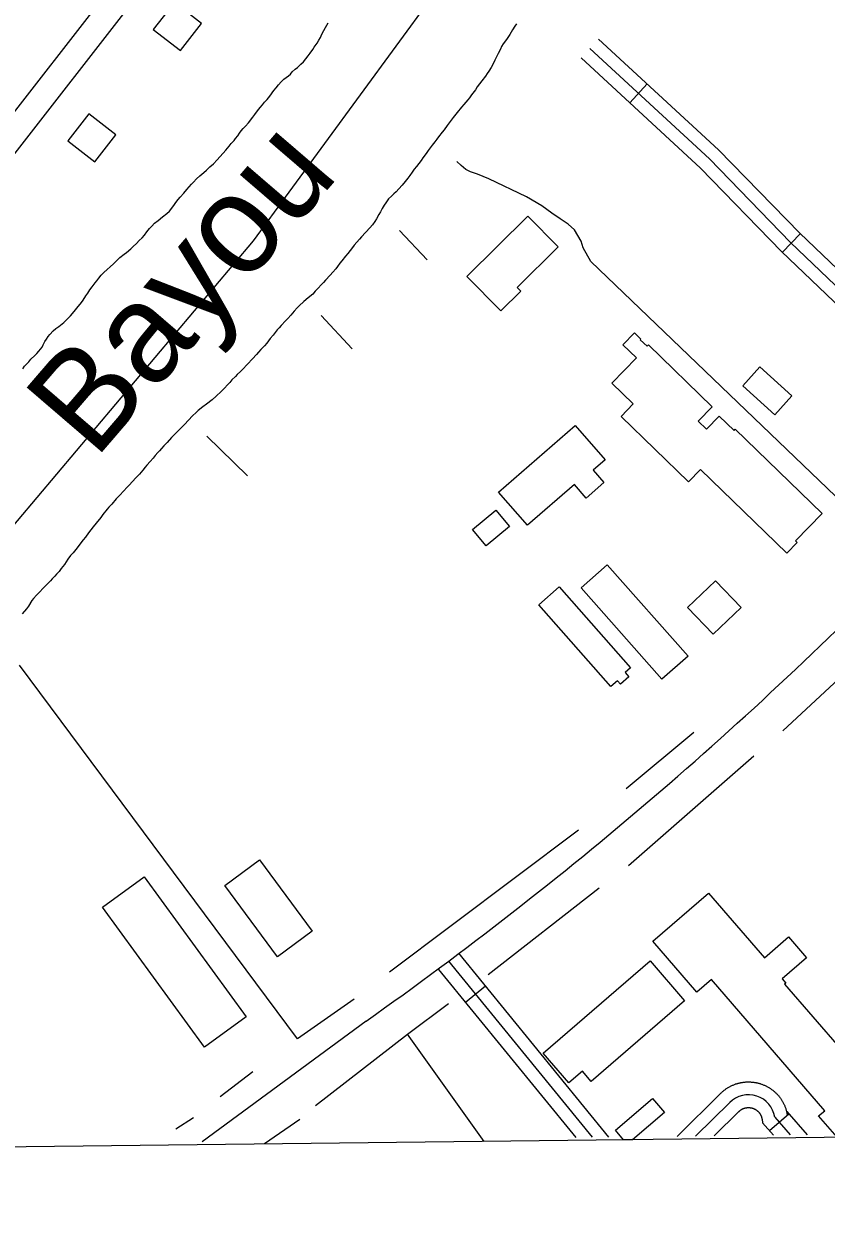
# Model space of a CAD drawing. Extents: x 3683402 to 3721514, y 487807 to 513565.
# Drawn here: x 3694421 to 3695359, y 493222 to 494613 of the extents above; entities that cross this region are included whole.
import ezdxf

# ---------------------------------------------------------------- set-up
doc = ezdxf.new("R2010")
doc.units = 0
for name, color, linetype in [('V-BLDG-OTLN', 7, 'Continuous'), ('V-GRID-FRAM', 7, 'Continuous'), ('V-RIVR-IDEN', 7, 'Continuous'), ('V-ROAD-CNTR', 7, 'Continuous'), ('V-TOPO-BNDY', 7, 'Continuous'), ('V-TOPO-SHOR', 7, 'Continuous')]:
    doc.layers.add(name, color=color, linetype=linetype)

msp = doc.modelspace()

# ---------------------------------------------------------------- linework, layer by layer
at = {"layer": 'V-BLDG-OTLN'}
for p, q in [((3695156.5, 493540.8), (3695221.6, 493597.1)), ((3695221.6, 493597.1), (3695286.8, 493521.6)), ((3695207.9, 493481.4), (3695156.5, 493540.8)), ((3695286.8, 493521.6), (3695314.8, 493545.8)), ((3695314.8, 493545.8), (3695335.9, 493521.4)), ((3695335.9, 493521.4), (3695307.6, 493496.9)), ((3695225, 493496), (3695207.9, 493481.4)), ((3695357.4, 493342.8), (3695225, 493496)), ((3695307.6, 493496.9), (3695311.8, 493492)), ((3695311.8, 493492), (3695310.3, 493490.6)), ((3695310.3, 493490.6), (3695376.3, 493414.2)), ((3695112.6, 493320.2), (3695156.1, 493357.2)), ((3695156.1, 493357.2), (3695170.1, 493340.8)), ((3695350.1, 493336.6), (3695357.4, 493342.8)), ((3695170.1, 493340.8), (3695132.5, 493308.9)), ((3695371.7, 493311.7), (3695350.1, 493336.6)), ((3695122.3, 493308.8), (3695112.6, 493320.2)), ((3695132.5, 493308.9), (3695122.3, 493308.8))]:
    msp.add_line(p, q, dxfattribs=at)
for points in [[(3694597.3, 494637.9), (3694572.7, 494606.4), (3694604.3, 494581.8), (3694628.9, 494613.4)], [(3694497.3, 494507.8), (3694472.7, 494476.2), (3694504.3, 494451.6), (3694528.8, 494483.2)], [(3694939.1, 494317.7), (3695010.3, 494388.2), (3695045.7, 494352.5), (3694997.7, 494304.9), (3695002.1, 494300.5), (3694978.9, 494277.5)], [(3695354.3, 494040.6), (3695323.2, 494008.6), (3695325, 494006.8), (3695312.9, 493994.4), (3695212.2, 494092.3), (3695197.9, 494077.6), (3695119.3, 494154.1), (3695133.6, 494168.8), (3695108.5, 494193.2), (3695137.2, 494222.7), (3695121.4, 494238), (3695134.9, 494251.9), (3695142.5, 494244.6), (3695141.7, 494243.7), (3695149.6, 494236.1), (3695151.3, 494237.8), (3695225.8, 494165.4), (3695209.5, 494148.7), (3695219.2, 494139.3), (3695234.1, 494154.6), (3695251.3, 494137.9), (3695252.7, 494139.4)], [(3695281.3, 494212), (3695318.8, 494178.2), (3695298.9, 494156.1), (3695261.4, 494189.8)], [(3695065.7, 494143.7), (3695100.6, 494103.6), (3695086.6, 494091.4), (3695099.3, 494076.8), (3695078.6, 494058.8), (3695064.8, 494074.6), (3695010, 494026.9), (3694976.2, 494065.7)], [(3694988.8, 494025.6), (3694961.5, 494002.9), (3694945.6, 494021.9), (3694972.9, 494044.7)], [(3695103.2, 493980.8), (3695197.7, 493874.1), (3695167.1, 493847.1), (3695072.6, 493953.7)], [(3695047, 493955), (3695130.4, 493860.5), (3695124.1, 493854.9), (3695128.5, 493849.9), (3695118.8, 493841.4), (3695115.3, 493845.3), (3695107.5, 493838.4), (3695023.2, 493933.9)], [(3695197, 493931), (3695229.8, 493962.2), (3695259.6, 493931), (3695226.9, 493899.7)], [(3694758.3, 493552.6), (3694717.8, 493522.7), (3694656.1, 493606.1), (3694696.7, 493636)], [(3694681.2, 493452.5), (3694632.6, 493417), (3694513.4, 493580.6), (3694562, 493616.1)], [(3695028.2, 493410.2), (3695153.2, 493518), (3695193.6, 493471.2), (3695084.4, 493376.9), (3695074.2, 493388.8), (3695058.4, 493375.2)]]:
    msp.add_lwpolyline(points, close=True, dxfattribs=at)
at = {"layer": 'V-GRID-FRAM'}
msp.add_lwpolyline([(3687448, 511403.5), (3719130.8, 511772.1), (3719350.3, 493590.7), (3687651.7, 493221.8), (3687448, 511403.5)], dxfattribs=at)
at = {"layer": 'V-ROAD-CNTR'}
for p, q in [((3695129.5, 494520.8), (3695149.8, 494542.8)), ((3695307.8, 494346.1), (3695328.5, 494367.7)), ((3694960.9, 493488.2), (3694937.6, 493469.2)), ((3695315.5, 493338.8), (3695292.9, 493319.1))]:
    msp.add_line(p, q, dxfattribs=at)
for points in [[(3694739.4, 494933.4), (3694169.7, 494201.4)], [(3694763.1, 494915), (3694193.4, 494182.9)], [(3696087.6, 493642.3), (3695328, 494368.3), (3695233.2, 494465.8), (3695093.1, 494595.2)], [(3696077.2, 493631.4), (3695317.4, 494357.6), (3695222.8, 494455.1), (3695082.9, 494584.1)], [(3696066.9, 493620.6), (3695306.9, 494347), (3695212.3, 494444.4), (3695072.8, 494573.1)], [(3694929.2, 493526.9), (3695104.7, 493311.9)], [(3694917.6, 493517.4), (3695085.5, 493311.7)], [(3694906, 493507.9), (3695066.3, 493311.5)], [(3694821.4, 493447.5), (3694629.7, 493306.4)], [(3695184.8, 493312.8), (3695235.7, 493363.1), (3695236.2, 493363.6), (3695236.9, 493364.1), (3695237.4, 493364.7), (3695238, 493365.2), (3695238.7, 493365.7), (3695239.2, 493366.2), (3695239.9, 493366.7), (3695240.5, 493367.2), (3695241.2, 493367.7), (3695241.8, 493368.2), (3695242.5, 493368.6), (3695243.1, 493369), (3695243.8, 493369.5), (3695244.5, 493369.9), (3695245.2, 493370.3), (3695245.9, 493370.7), (3695246.6, 493371.1), (3695247.3, 493371.5), (3695248.1, 493371.8), (3695248.8, 493372.2), (3695249.5, 493372.5), (3695250.2, 493372.8), (3695251, 493373.1), (3695251.7, 493373.4), (3695252.5, 493373.7)], [(3695252.5, 493373.7), (3695253.2, 493374), (3695254, 493374.2), (3695254.8, 493374.5), (3695255.6, 493374.7), (3695256.3, 493374.9), (3695257.1, 493375.1), (3695257.9, 493375.3), (3695258.7, 493375.5), (3695259.4, 493375.6), (3695260.2, 493375.8), (3695261, 493375.9), (3695261.8, 493376), (3695262.6, 493376.1), (3695263.4, 493376.2), (3695264.2, 493376.3), (3695265, 493376.4), (3695265.8, 493376.4), (3695266.6, 493376.4), (3695267.4, 493376.5), (3695268.2, 493376.5), (3695269, 493376.5), (3695269.8, 493376.4), (3695270.6, 493376.4), (3695271.4, 493376.3), (3695272.2, 493376.3), (3695273, 493376.2), (3695273.8, 493376.1), (3695274.6, 493376), (3695275.4, 493375.9), (3695276.2, 493375.8), (3695277, 493375.6), (3695277.7, 493375.5), (3695278.6, 493375.3), (3695279.4, 493375.1), (3695280.1, 493374.9), (3695280.9, 493374.7), (3695281.7, 493374.4), (3695282.4, 493374.2), (3695283.2, 493373.9), (3695283.9, 493373.7), (3695284.7, 493373.4), (3695285.4, 493373.1), (3695286.2, 493372.8), (3695286.9, 493372.5), (3695287.6, 493372.1), (3695288.4, 493371.8), (3695289.1, 493371.4), (3695289.8, 493371.1), (3695290.5, 493370.7), (3695291.2, 493370.3), (3695291.9, 493369.9), (3695292.6, 493369.5), (3695293.3, 493369), (3695293.9, 493368.6), (3695294.6, 493368.1), (3695295.2, 493367.7), (3695295.9, 493367.2), (3695296.5, 493366.7), (3695297.2, 493366.2), (3695297.7, 493365.7), (3695298.4, 493365.1), (3695299, 493364.6), (3695299.5, 493364.1), (3695300.2, 493363.5), (3695300.7, 493363), (3695301.3, 493362.4), (3695301.9, 493361.8), (3695302.4, 493361.2), (3695302.9, 493360.6), (3695303.5, 493360), (3695303.9, 493359.4), (3695304.4, 493358.8), (3695304.9, 493358.1), (3695305.4, 493357.5), (3695305.9, 493356.8), (3695306.3, 493356.2), (3695306.8, 493355.5), (3695307.2, 493354.8), (3695307.6, 493354.1), (3695308, 493353.4), (3695308.4, 493352.7), (3695308.8, 493352), (3695309.2, 493351.3), (3695309.5, 493350.6), (3695309.9, 493349.9), (3695310.2, 493349.1), (3695310.5, 493348.4), (3695310.8, 493347.7), (3695311.1, 493346.9), (3695311.4, 493346.2), (3695311.7, 493345.4), (3695311.9, 493344.7), (3695312.2, 493343.9), (3695312.4, 493343.1), (3695312.6, 493342.3), (3695312.8, 493341.6), (3695313, 493340.8), (3695313.2, 493340), (3695313.3, 493339.2), (3695313.5, 493338.4)], [(3695206.4, 493313.1), (3695246.3, 493352.4)], [(3695228, 493313.3), (3695256.8, 493341.7), (3695257.1, 493342), (3695257.2, 493342.1), (3695257.5, 493342.4), (3695257.7, 493342.6), (3695257.9, 493342.7), (3695258.1, 493342.9), (3695258.4, 493343.1), (3695258.5, 493343.2), (3695258.8, 493343.4), (3695259, 493343.6), (3695259.3, 493343.7), (3695259.5, 493343.9), (3695259.7, 493344), (3695259.9, 493344.2), (3695260.2, 493344.3), (3695260.4, 493344.5), (3695260.7, 493344.6), (3695260.9, 493344.7), (3695261.2, 493344.8), (3695261.4, 493345), (3695261.7, 493345.1), (3695261.9, 493345.2), (3695262.2, 493345.3), (3695262.4, 493345.4), (3695262.7, 493345.5)], [(3695262.7, 493345.5), (3695263, 493345.6), (3695263.3, 493345.7), (3695263.5, 493345.8), (3695263.7, 493345.8), (3695264.1, 493345.9), (3695264.3, 493346), (3695264.6, 493346.1), (3695264.8, 493346.1), (3695265.1, 493346.2), (3695265.4, 493346.2), (3695265.7, 493346.3), (3695266, 493346.3), (3695266.3, 493346.3), (3695266.5, 493346.4), (3695266.8, 493346.4), (3695267.1, 493346.4), (3695267.4, 493346.4), (3695267.6, 493346.4), (3695267.9, 493346.5), (3695268.2, 493346.5), (3695268.5, 493346.5), (3695268.7, 493346.4), (3695269, 493346.4), (3695269.3, 493346.4), (3695269.6, 493346.4), (3695269.9, 493346.4), (3695270.1, 493346.3), (3695270.4, 493346.3), (3695270.7, 493346.3), (3695271, 493346.2), (3695271.2, 493346.2), (3695271.5, 493346.1), (3695271.8, 493346), (3695272, 493346), (3695272.3, 493345.9), (3695272.6, 493345.8), (3695272.9, 493345.8), (3695273.1, 493345.7), (3695273.4, 493345.6), (3695273.7, 493345.5), (3695273.9, 493345.4), (3695274.2, 493345.3), (3695274.4, 493345.2), (3695274.7, 493345.1), (3695274.9, 493345), (3695275.2, 493344.8), (3695275.4, 493344.7), (3695275.7, 493344.6), (3695275.9, 493344.5), (3695276.2, 493344.3), (3695276.5, 493344.1), (3695276.7, 493344), (3695276.9, 493343.9), (3695277.1, 493343.7), (3695277.4, 493343.5), (3695277.6, 493343.4), (3695277.8, 493343.2), (3695278, 493343.1), (3695278.2, 493342.9), (3695278.5, 493342.7), (3695278.7, 493342.5), (3695278.9, 493342.3), (3695279.1, 493342.1), (3695279.3, 493342), (3695279.5, 493341.8), (3695279.7, 493341.6), (3695279.9, 493341.4), (3695280.1, 493341.1), (3695280.3, 493340.9), (3695280.4, 493340.8), (3695280.6, 493340.5), (3695280.8, 493340.3), (3695280.9, 493340.1), (3695281.1, 493339.9), (3695281.3, 493339.6), (3695281.5, 493339.4), (3695281.6, 493339.1), (3695281.7, 493339), (3695281.9, 493338.7), (3695282, 493338.4), (3695282.2, 493338.2), (3695282.3, 493338), (3695282.4, 493337.7), (3695282.5, 493337.5), (3695282.7, 493337.2), (3695282.8, 493337), (3695282.9, 493336.7), (3695283, 493336.4), (3695283.1, 493336.2), (3695283.2, 493335.9), (3695283.3, 493335.7), (3695283.4, 493335.4), (3695283.5, 493335.1), (3695283.5, 493334.9), (3695283.6, 493334.6), (3695283.7, 493334.3), (3695283.8, 493334.1), (3695283.8, 493333.8), (3695283.9, 493333.5), (3695283.9, 493333.2)], [(3695283.9, 493333.2), (3695284, 493332.9), (3695284.7, 493328.6), (3695297.3, 493314.2)], [(3695298.8, 493335.2), (3695317, 493314.4)], [(3695313.5, 493338.4), (3695313.6, 493337.7), (3695313, 493341.8), (3695336.7, 493314.6)]]:
    msp.add_lwpolyline(points, dxfattribs=at)
for centre, radius, start, end in [((3692172.5, 497192.6), 4587.2, 305.2715, 315.862), ((3695268.2, 493330.5), 31, 8.7896, 134.9574)]:
    msp.add_arc(centre, radius, start, end, dxfattribs=at)
at = {"layer": 'V-TOPO-BNDY'}
for p, q in [((3695081.5, 494895.1), (3694689.5, 494359.4)), ((3694689.5, 494359.4), (3694227.8, 493811.9))]:
    msp.add_line(p, q, dxfattribs=at)
at = {"layer": 'V-TOPO-SHOR'}
for p, q in [((3694860.3, 494371.3), (3694892.6, 494337.2)), ((3694768.9, 494272), (3694805, 494233.2)), ((3694635.2, 494131.1), (3694682.8, 494084.7)), ((3695308.4, 493786.6), (3695391.1, 493863.9)), ((3695204.2, 493784.6), (3695125.4, 493719.1)), ((3695127.9, 493629.4), (3695274.5, 493757.6)), ((3695069.5, 493670.6), (3694848.7, 493504.7)), ((3694964, 493501.8), (3695093.6, 493603.3)), ((3694869.8, 493432), (3694762.4, 493348.3)), ((3694689.1, 493388.1), (3694650.8, 493358.8)), ((3694619.5, 493334.6), (3694599.1, 493321.4))]:
    msp.add_line(p, q, dxfattribs=at)
for points in [[(3694501.3, 494305.7), (3694504.7, 494310.2), (3694506.5, 494312.6), (3694508.9, 494315.9), (3694511.7, 494319.3), (3694514.9, 494322.3), (3694518.7, 494325.8), (3694522.2, 494329), (3694526, 494332.6), (3694531.2, 494337.7), (3694533.5, 494339.9), (3694538.6, 494343.9), (3694541.4, 494345.9), (3694546.3, 494349.9), (3694549.3, 494352.6), (3694552.9, 494356.4), (3694556.2, 494359.6), (3694559.8, 494362.9), (3694562.4, 494366.1), (3694565, 494369.8), (3694568.4, 494373.6), (3694571, 494376.5), (3694574.2, 494379.9), (3694578.5, 494383.1), (3694583.6, 494387.3), (3694588.5, 494391.2), (3694591.5, 494394.2), (3694596.5, 494400.5), (3694598.9, 494404), (3694601.9, 494407.8), (3694604.1, 494410.5), (3694608.2, 494414.9), (3694612, 494419.2), (3694617.4, 494425.5), (3694619.6, 494427.9), (3694623.2, 494432), (3694626.9, 494435.2), (3694631.8, 494439.2), (3694635, 494442), (3694638.8, 494445.7), (3694643.1, 494449.5), (3694647.2, 494454.2), (3694650.4, 494457.4), (3694654.3, 494461.9), (3694657.3, 494465.3), (3694661.4, 494470), (3694663.8, 494473.2), (3694667, 494476.7), (3694668.8, 494479.1), (3694671.3, 494482.2), (3694673.5, 494485), (3694675.5, 494488.1), (3694677.8, 494490.7), (3694680.6, 494493.5), (3694684.1, 494497.4), (3694689.1, 494503.7), (3694691.4, 494507), (3694694.5, 494511.2), (3694697.5, 494515.1), (3694700.1, 494518.4), (3694702.7, 494521.4), (3694705.7, 494524.5), (3694708.7, 494528.3), (3694713.7, 494535), (3694716.3, 494538.3), (3694719.1, 494541.5), (3694722.1, 494545), (3694725.3, 494548.2), (3694730.7, 494552.2), (3694733, 494554.2), (3694735, 494556.7), (3694738.6, 494559.9), (3694741.1, 494561.9), (3694745.2, 494566), (3694748, 494568.4), (3694751, 494572.2), (3694753.8, 494575.7), (3694756, 494578.8), (3694759, 494582.8), (3694760.8, 494585.7), (3694764.1, 494590.4), (3694766, 494593.7), (3694768.2, 494597.1), (3694769.8, 494600.8), (3694772, 494605.3), (3694774, 494608.6), (3694775.5, 494611.3), (3694777.2, 494614.1)], [(3694997.2, 494613), (3694995.3, 494610.2), (3694992.6, 494606.1), (3694989.4, 494600.6), (3694986.3, 494595.9), (3694984.4, 494593.2), (3694981.5, 494589.6), (3694979.6, 494586.5), (3694978.2, 494583.4), (3694975.6, 494578.3), (3694973.6, 494574.2), (3694971.8, 494570.5), (3694969.8, 494566.2), (3694967.6, 494562.1), (3694964.8, 494557.6), (3694963, 494554.9), (3694960.9, 494551.7), (3694956.7, 494546.2), (3694951.3, 494539.3), (3694949.1, 494536), (3694944.6, 494530.1), (3694942, 494526.6), (3694940.3, 494524.2), (3694935.7, 494518.7), (3694932.9, 494515.7), (3694927.8, 494509.4), (3694923.2, 494503.5), (3694920.6, 494500.4), (3694916.1, 494494.1), (3694912.4, 494489.2), (3694910.4, 494486.3), (3694906.1, 494480.9), (3694903.9, 494478), (3694901.6, 494475.2), (3694898.7, 494471.3), (3694894, 494465), (3694891.4, 494461.3), (3694887.5, 494456.2), (3694885.7, 494453.4), (3694880.1, 494446.4), (3694877.5, 494443), (3694875.1, 494439.7), (3694872.5, 494435.8), (3694870.3, 494432.6), (3694867.1, 494428.7), (3694863.6, 494424.4), (3694859.5, 494420), (3694856.3, 494416.5), (3694853.7, 494414.1), (3694851, 494411.5), (3694847.7, 494408.3), (3694844.5, 494403.6), (3694842.5, 494400.9), (3694840.3, 494397.2), (3694838.3, 494393.1), (3694836.4, 494390.1), (3694833.5, 494385.2), (3694831.4, 494382.1), (3694828.8, 494378.2), (3694825.7, 494374.6), (3694815.8, 494364), (3694813.5, 494361.4), (3694810.7, 494357.9), (3694807.4, 494354.3), (3694805.5, 494351.4), (3694800.1, 494344.5), (3694797.3, 494341.3), (3694792.9, 494336), (3694790.8, 494333.1), (3694787.8, 494329.3), (3694785.8, 494326.8), (3694782.4, 494322.8), (3694779.3, 494319.3), (3694774, 494313.4), (3694771.4, 494310.6), (3694769, 494308), (3694765.2, 494304.1)], [(3694997.2, 494613), (3694995.3, 494610.2), (3694992.6, 494606.1), (3694989.4, 494600.6), (3694986.3, 494595.9), (3694984.4, 494593.2), (3694981.5, 494589.6), (3694979.6, 494586.5), (3694978.2, 494583.4), (3694975.6, 494578.3), (3694973.6, 494574.2), (3694971.8, 494570.5), (3694969.8, 494566.2), (3694967.6, 494562.1), (3694964.8, 494557.6), (3694963, 494554.9), (3694960.9, 494551.7), (3694956.7, 494546.2), (3694951.3, 494539.3), (3694949.1, 494536), (3694944.6, 494530.1), (3694942, 494526.6), (3694940.3, 494524.2), (3694935.7, 494518.7), (3694932.9, 494515.7), (3694927.8, 494509.4), (3694923.2, 494503.5), (3694920.6, 494500.4), (3694916.1, 494494.1), (3694912.4, 494489.2), (3694910.4, 494486.3), (3694906.1, 494480.9), (3694903.9, 494478), (3694901.6, 494475.2), (3694898.7, 494471.3), (3694894, 494465), (3694891.4, 494461.3)], [(3694891.4, 494461.3), (3694887.5, 494456.2), (3694885.7, 494453.4), (3694880.1, 494446.4), (3694877.5, 494443), (3694875.1, 494439.7), (3694872.5, 494435.8), (3694870.3, 494432.6), (3694867.1, 494428.7), (3694863.6, 494424.4), (3694859.5, 494420), (3694856.3, 494416.5), (3694853.7, 494414.1), (3694851, 494411.5), (3694847.7, 494408.3), (3694844.5, 494403.6), (3694842.5, 494400.9), (3694840.3, 494397.2), (3694838.3, 494393.1), (3694836.4, 494390.1), (3694833.5, 494385.2), (3694831.4, 494382.1), (3694828.8, 494378.2), (3694825.7, 494374.6), (3694815.8, 494364), (3694813.5, 494361.4), (3694810.7, 494357.9), (3694807.4, 494354.3), (3694805.5, 494351.4), (3694800.1, 494344.5), (3694797.3, 494341.3), (3694792.9, 494336), (3694790.8, 494333.1), (3694787.8, 494329.3), (3694785.8, 494326.8), (3694782.4, 494322.8), (3694779.3, 494319.3), (3694774, 494313.4), (3694771.4, 494310.6), (3694769, 494308), (3694765.2, 494304.1), (3694761.9, 494300.7), (3694758.9, 494297.2), (3694753.6, 494292.6), (3694748.5, 494288.4), (3694743.3, 494283.5), (3694740.7, 494281.1), (3694737.3, 494277.1), (3694733.4, 494272.4), (3694730, 494268.5), (3694727.2, 494265.9), (3694722, 494260.6), (3694719.7, 494257.8), (3694717.5, 494255.4), (3694715.1, 494252.1), (3694712.7, 494249.3), (3694709.3, 494245.2), (3694707.1, 494242.4), (3694705.4, 494239.9), (3694702.8, 494236.7), (3694698.5, 494232.2), (3694695.7, 494229.2), (3694693.3, 494226.7), (3694688.4, 494221.3), (3694682.8, 494215.4), (3694677, 494209.1), (3694674.4, 494206.7), (3694670.8, 494203.3), (3694668.6, 494200.8), (3694664.6, 494197), (3694662, 494193.9), (3694659.8, 494191.3), (3694655.5, 494186.6), (3694652.1, 494183.4), (3694646.3, 494177.7), (3694641.6, 494173.5), (3694634.8, 494168.3), (3694630.5, 494165.3), (3694625, 494160.9), (3694622.2, 494158.3), (3694618.8, 494155.2), (3694613.4, 494149.4), (3694609.5, 494145.3), (3694602.7, 494138), (3694599.9, 494135.4), (3694596.7, 494132.2), (3694594.1, 494129.5), (3694588.7, 494123.5), (3694585.1, 494119.8), (3694582.3, 494116.6), (3694580.1, 494114.1), (3694578, 494111.9), (3694574.7, 494108.3), (3694572.4, 494105.4), (3694569.1, 494101.6), (3694565.2, 494097.3), (3694563.3, 494094.9), (3694560.3, 494091.4), (3694558.5, 494089), (3694556.4, 494086.5), (3694552.3, 494082.5)], [(3695534.1, 494116.8), (3695427.3, 494006.1), (3695084, 494335.1), (3695075.1, 494351.2), (3695072.8, 494358.8), (3695064.9, 494372.3), (3695057.4, 494379), (3695048, 494384.9), (3695038.2, 494391.8), (3695026.6, 494400.3), (3695008.6, 494410.8), (3694964.9, 494431.9), (3694951.7, 494437.3), (3694943.3, 494440), (3694937.7, 494442.7), (3694932.5, 494447.4), (3694927.4, 494451.9)], [(3694765.2, 494304.1), (3694761.9, 494300.7), (3694758.9, 494297.2), (3694753.6, 494292.6), (3694748.5, 494288.4), (3694743.3, 494283.5), (3694740.7, 494281.1), (3694737.3, 494277.1), (3694733.4, 494272.4), (3694730, 494268.5), (3694727.2, 494265.9), (3694722, 494260.6), (3694719.7, 494257.8), (3694717.5, 494255.4), (3694715.1, 494252.1), (3694712.7, 494249.3), (3694709.3, 494245.2), (3694707.1, 494242.4), (3694705.4, 494239.9), (3694702.8, 494236.7), (3694698.5, 494232.2), (3694695.7, 494229.2), (3694693.3, 494226.7), (3694688.4, 494221.3), (3694682.8, 494215.4), (3694677, 494209.1), (3694674.4, 494206.7), (3694670.8, 494203.3), (3694668.6, 494200.8), (3694664.6, 494197), (3694662, 494193.9), (3694659.8, 494191.3), (3694655.5, 494186.6), (3694652.1, 494183.4), (3694646.3, 494177.7), (3694641.6, 494173.5), (3694634.8, 494168.3), (3694630.5, 494165.3), (3694625, 494160.9), (3694622.2, 494158.3), (3694618.8, 494155.2), (3694613.4, 494149.4), (3694609.5, 494145.3), (3694602.7, 494138), (3694599.9, 494135.4), (3694596.7, 494132.2), (3694594.1, 494129.5), (3694588.7, 494123.5), (3694585.1, 494119.8), (3694582.3, 494116.6), (3694580.1, 494114.1), (3694578, 494111.9), (3694574.7, 494108.3), (3694572.4, 494105.4), (3694569.1, 494101.6), (3694565.2, 494097.3), (3694563.3, 494094.9), (3694560.3, 494091.4), (3694558.5, 494089), (3694556.4, 494086.5), (3694552.3, 494082.5), (3694544.4, 494074), (3694542, 494071.5), (3694533.4, 494062.2), (3694529.3, 494057.8), (3694524.1, 494051.7), (3694520.9, 494048.2), (3694518.8, 494045.6), (3694513.8, 494039.5), (3694511.2, 494036.2), (3694506, 494029.5), (3694502.3, 494025), (3694496.9, 494018.3), (3694493.4, 494013.2), (3694490.8, 494009.8), (3694482.2, 493998.6), (3694479, 493994.9), (3694476.1, 493991.5), (3694472.9, 493987.2), (3694468.8, 493981.3), (3694465.1, 493976.6), (3694462.5, 493973.1), (3694459.7, 493969.9), (3694457.7, 493967.5), (3694454.5, 493964.4), (3694452.6, 493962), (3694449.4, 493959), (3694443.4, 493952.9), (3694439.9, 493949.2), (3694436.1, 493945.2), (3694432.8, 493941.3), (3694430.9, 493938.9), (3694426.9, 493932.6), (3694424.6, 493929.3), (3694419.6, 493923.4)], [(3694420.2, 494209.8), (3694422.3, 494212.7), (3694424.9, 494215.7), (3694427.1, 494217.9), (3694429.7, 494221), (3694434.2, 494225.4), (3694436.5, 494227.7), (3694438.9, 494230.5), (3694442.8, 494235.2), (3694444.1, 494238), (3694446.1, 494241.7), (3694447.8, 494244.4), (3694450, 494247.5), (3694451.7, 494249.9), (3694455.6, 494254.2), (3694458.8, 494257), (3694462.4, 494259.2), (3694468.2, 494264), (3694472.7, 494268.6), (3694475.9, 494271.9), (3694480.2, 494276.7), (3694483.5, 494280.6), (3694488.9, 494287.1), (3694490.8, 494290), (3694493.9, 494295.1), (3694496.1, 494298.3), (3694498.7, 494302.2), (3694501.3, 494305.7)], [(3694552.3, 494082.5), (3694544.4, 494074), (3694542, 494071.5), (3694533.4, 494062.2), (3694529.3, 494057.8), (3694524.1, 494051.7), (3694520.9, 494048.2), (3694518.8, 494045.6), (3694513.8, 494039.5), (3694511.2, 494036.2), (3694506, 494029.5), (3694502.3, 494025), (3694496.9, 494018.3), (3694493.4, 494013.2), (3694490.8, 494009.8), (3694482.2, 493998.6), (3694479, 493994.9), (3694476.1, 493991.5), (3694472.9, 493987.2), (3694468.8, 493981.3), (3694465.1, 493976.6), (3694462.5, 493973.1), (3694459.7, 493969.9), (3694457.7, 493967.5), (3694454.5, 493964.4), (3694452.6, 493962), (3694449.4, 493959), (3694443.4, 493952.9), (3694439.9, 493949.2), (3694436.1, 493945.2), (3694432.8, 493941.3), (3694430.9, 493938.9), (3694426.9, 493932.6), (3694424.6, 493929.3), (3694419.6, 493923.4)], [(3694807.5, 493473), (3694741, 493426.9), (3694416.5, 493863.6)], [(3694959.5, 493306.9), (3694869.7, 493432.1), (3694917.6, 493467.9)], [(3694744, 493332.4), (3694702.8, 493303.9)]]:
    msp.add_lwpolyline(points, dxfattribs=at)

# ---------------------------------------------------------------- texts
at = {"layer": 'V-RIVR-IDEN'}
msp.add_text('Bayou', height=116, rotation=49.316, dxfattribs=at).set_placement((3694504.4, 494102.7))

doc.saveas('drawing.dxf')
